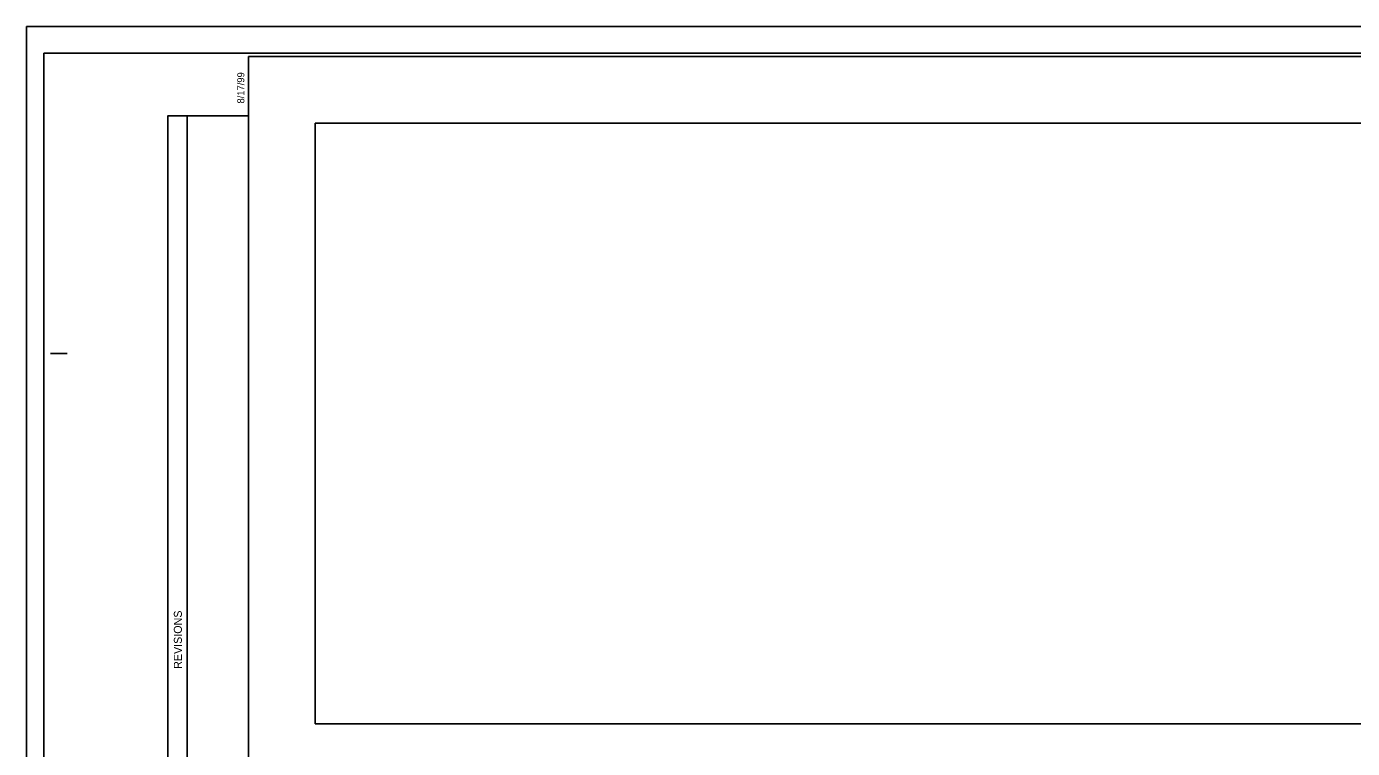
# Model space of a CAD drawing. Extents: x 757145 to 758829, y 592169 to 594973.
# Drawn here: x 757145 to 758139, y 593262 to 593803 of the extents above; entities that cross this region are included whole.
import ezdxf

# ---------------------------------------------------------------- set-up
doc = ezdxf.new("R2010")
doc.units = 0
for name, color, linetype in [('Exist Vertical Profile Horizontal Axis Label Major', 7, 'Continuous'), ('Exist Vertical Profile Vertical Axis Label', 7, 'Continuous'), ('Sheet Cutting Line CELL', 7, 'Continuous'), ('Sheet Plan And Profile CELL', 7, 'Continuous'), ('Sheet Plot Border Inside CELL', 7, 'Continuous'), ('Sheet Plot Border Outside CELL', 7, 'Continuous')]:
    doc.layers.add(name, color=color, linetype=linetype)

msp = doc.modelspace()

# ---------------------------------------------------------------- linework, layer by layer
at = {"layer": 'Exist Vertical Profile Horizontal Axis Label Major'}
msp.add_lwpolyline([(757361.92, 593280.33), (757361.92, 593730.33), (758561.87, 593730.33), (758561.87, 593580.28), (758761.92, 593580.28), (758761.92, 593280.33)], close=True, dxfattribs=at)
at = {"layer": 'Exist Vertical Profile Vertical Axis Label'}
msp.add_line((757265.92, 592945.33), (757265.92, 593735.98), dxfattribs=at)
msp.add_lwpolyline([(757251.37, 592945.33), (757251.37, 593735.98), (757311.92, 593735.98), (757311.92, 592945.33)], close=True, dxfattribs=at)
at = {"layer": 'Sheet Cutting Line CELL'}
for p, q in [((758828.92, 593802.83), (757145.42, 593802.83)), ((757145.42, 593802.83), (757145.42, 592707.83))]:
    msp.add_line(p, q, dxfattribs=at)
at = {"layer": 'Sheet Plan And Profile CELL'}
msp.add_line((757163.42, 593557.83), (757175.92, 593557.83), dxfattribs=at)
msp.add_lwpolyline([(758811.92, 593780.33), (757311.92, 593780.33), (757311.92, 592730.33), (758811.92, 592730.33)], close=True, dxfattribs=at)
at = {"layer": 'Sheet Plot Border Inside CELL'}
msp.add_lwpolyline([(757158.42, 592727.83), (758824.42, 592727.83), (758824.42, 593782.83), (757158.42, 593782.83)], close=True, dxfattribs=at)
at = {"layer": 'Sheet Plot Border Outside CELL'}
msp.add_lwpolyline([(757145.42, 592707.83), (758828.92, 592707.83), (758828.92, 593802.83), (757145.42, 593802.83)], close=True, dxfattribs=at)

# ---------------------------------------------------------------- texts
at = {"layer": 'Exist Vertical Profile Vertical Axis Label'}
msp.add_text('REVISIONS', height=6, rotation=90, dxfattribs=at).set_placement((757261.87, 593321.48))
at = {"layer": 'Sheet Plan And Profile CELL'}
msp.add_text('8/17/99', height=5.25, rotation=90, dxfattribs=at).set_placement((757308.67, 593745.13))

doc.saveas('drawing.dxf')
